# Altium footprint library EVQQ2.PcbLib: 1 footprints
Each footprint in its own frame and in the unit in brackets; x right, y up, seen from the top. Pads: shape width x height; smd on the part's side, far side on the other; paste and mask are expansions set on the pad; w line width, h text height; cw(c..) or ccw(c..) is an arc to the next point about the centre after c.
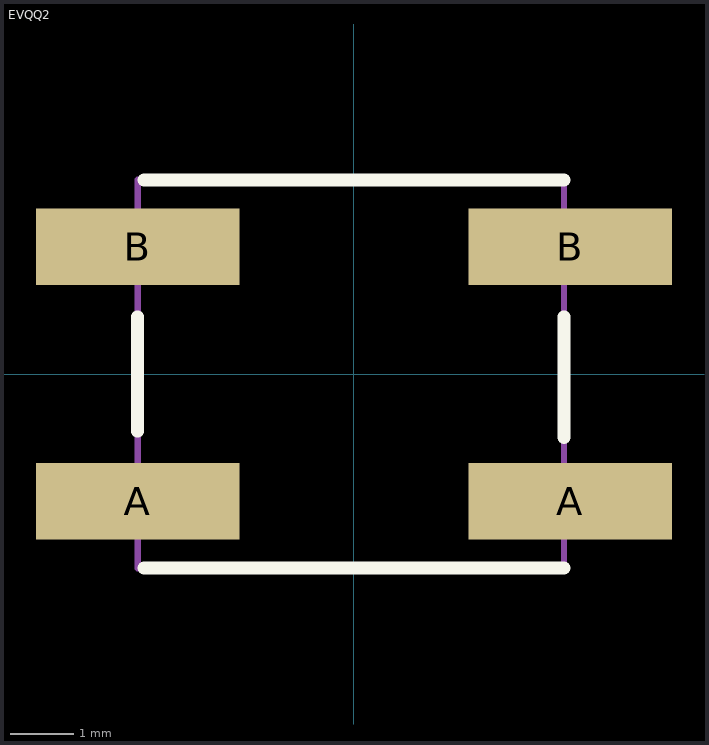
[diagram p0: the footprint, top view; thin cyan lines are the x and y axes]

## EVQQ2 [mm] "Panasonic EVQQ2 Tactile Button"
pads (4):
  rect 3.2x1.2 smd: A(-3.4,-2) A(3.4,-2) B(-3.4,2) B(3.4,2)
Top Overlay:
  lines w0.203: -3.4,-0.9 -3.4,0.9 ; -3.3,-3.05 3.3,-3.05 ; -3.3,3.05 3.3,3.05 ; 3.3,-1 3.3,0.9
Mechanical 31:
  lines w0.102: -3.4,-3.05 -3.4,3.05 3.3,3.05 3.3,-3.05 -3.4,-3.05
  text ".Designator" at -2.7,0.7 h0.76
  text ".Comment" at -2.7,-1.5 h0.76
